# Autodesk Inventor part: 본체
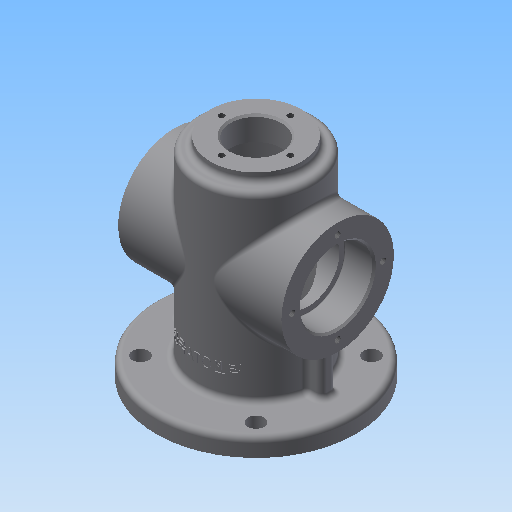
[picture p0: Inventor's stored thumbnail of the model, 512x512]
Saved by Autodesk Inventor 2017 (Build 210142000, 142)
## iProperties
Created: 2020-05
Part Number: 본체
Material: 알루미늄 6061
Document SubType Name: Modeling
Designer: mduedu
Density: 2.71 g/cm^3
Appearance: 기본값
Mass: 777.255 g
Surface Area: 687.925 cm^2
Volume: 286.81 cm^3
Author: mduedu
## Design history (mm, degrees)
sketch "스케치1"
  geometry: C1 r 32 at (0, 0); 1 further point
  constraints: 1 centre point, 1 coincident
  dimensions: "d0" = 64 diameter of C1
extrude "돌출1" new body sketch "스케치1" distance "d1" = 110; taper "d2" = 0 deg
feature "쉘1" dims "d3" = 8
fillet "모깎기1" dims "d4" = 3
fillet "모깎기2" dims "d5" = 3
sketch "스케치2"
  geometry: C1 r 25 at (0, 0); 1 further point
  constraints: 1 centre point, 1 coincident
  dimensions: "d6" = 50 diameter of C1
extrude "돌출2" join sketch "스케치2" distance "d7" = 5; taper "d8" = 0 deg
sketch "스케치3"
  geometry: C1 r 14 at (0, 0); 1 further point
  constraints: 1 centre point, 1 coincident
  dimensions: "d9" = 28 diameter of C1
extrude "돌출3" cut sketch "스케치3" stored distance "d10" = 5; taper "d11" = 0 deg
fillet "모깎기3" dims "d12" = 3
sketch "스케치4"
  geometry: C1 r 32 at (0, 0) reference; C2 r 55 at (0, 0); 1 further point
  constraints: 1 centre point, 1 coincident
  dimensions: "d13" = 110 diameter of C2
extrude "돌출4" join sketch "스케치4" distance "d14" = 10; taper "d15" = 0 deg
sketch "스케치5"
  geometry: L1 (0, 0)-(-31.82, 31.82); L2 (0, 0)-(-45, 0); A1 r 45 centre (0, 0) between (-31.82, 31.82) and (-45, 0); 1 further point
  constraints: 4 end point, 2 point on circle, 1 centre point, 1 coincident, 1 horizontal
  dimensions: "d16" = 90 diameter of A1; "d71" = 45 deg angle of L1 L2
hole "구멍1" sketch "스케치5" at (-31.82, 31.82) diameter "d17" = 9; stored, may be unused: countersink angle "d21" = 90 deg, drill point angle "d23" = 118 deg; dims "d18" = 6, "d19" = 4, "d20" = 2, "d22" = 8
fillet "모깎기4" dims "d27" = 3
node "작업 평면1"
sketch "스케치6"
  geometry: L1 (0, 55)-(0, -55) reference; C1 r 31 at (-65, 0); 2 further points
  constraints: 1 centre point, 1 horizontal alignment, 1 midpoint
  dimensions: "d31" = 62 diameter of C1; "d32" = 65 distance from line of C1.centre L1
extrude "돌출5" join sketch "스케치6" stored distance "d33" = 10; taper "d34" = 0 deg
fillet "모깎기5" dims "d35" = 3
sketch "스케치7"
  geometry: C1 r 31 at (0, 0) reference; C2 r 20 at (0, 0); 1 further point
  constraints: 1 centre point, 1 coincident
  dimensions: "d36" = 40 diameter of C2
extrude "돌출6" cut sketch "스케치7" distance "d37" = 16; taper "d38" = 0 deg
sketch "스케치8"
  geometry: C1 r 20 at (0, 0) reference; C2 r 17 at (0, 0); 1 further point
  constraints: 1 centre point, 1 coincident
  dimensions: "d39" = 34 diameter of C2
extrude "돌출7" cut sketch "스케치8" stored distance "d40" = 15; taper "d41" = 0 deg
fillet "모깎기6" dims "d42" = 0.3
chamfer "모따기1" distance "d43" = 1; stored, may be unused: second distance "d44" = 2, angle "d45" = 45 deg
chamfer "모따기2" distance "d46" = 1; stored, may be unused: second distance "d47" = 2, angle "d48" = 45 deg
sketch "스케치9" dims "d49" = 50
  geometry: C1 r 31 at (0, 0) reference; 3 further points
  constraints: 2 vertical alignment, 1 coincident, 2 other
hole "구멍2" sketch "스케치9" at (0, 25) diameter "d50" = 3.242; stored, may be unused: countersink angle "d54" = 90 deg, drill point angle "d56" = 118 deg; dims "d51" = 7, "d52" = 4, "d53" = 2, "d55" = 9
sketch "스케치10" dims "d60" = 38
  geometry: 3 further points
  constraints: 2 vertical alignment, 1 coincident, 2 other
hole "구멍3" sketch "스케치10" at (0, 19) diameter "d61" = 3.242; stored, may be unused: countersink angle "d65" = 90 deg, drill point angle "d67" = 118 deg; dims "d62" = 8, "d63" = 4, "d64" = 2, "d66" = 10
sketch "스케치11"
  geometry: L1 (32, 31)-(32, 13) reference; L2 (35, 10)-(52, 10) reference; L3 (55, 7)-(55, 0) reference; L4 (55, 0)-(24, 0) reference; L5 (24, 0)-(24, 48) reference; L6 (24, 48)-(29, 48) reference; L7 (29, 48)-(29, 45.3) reference; L8 (29.3, 45)-(44, 45) reference; L9 (44, 45)-(45, 44) reference; L10 (45, 44)-(45, 41.621) reference; L11 (45, 41.621)-(36, 41.621) reference; L12 (36, 41.621)-(35.026, 40) reference; L13 (35.026, 40)-(36, 38.379) reference; L14 (36, 38.379)-(45, 38.379) reference; L15 (45, 38.379)-(45, 34) reference; L16 (45, 34)-(35, 34) reference; L17 (-32, 13)-(-32, 31) reference; L18 (-35, 34)-(-45, 34) reference; L19 (-45, 34)-(-45, 38.379) reference; L20 (-45, 38.379)-(-36, 38.379) reference; L21 (-36, 38.379)-(-35.026, 40) reference; L22 (-35.026, 40)-(-36, 41.621) reference; L23 (-36, 41.621)-(-45, 41.621) reference; L24 (-45, 41.621)-(-45, 44) reference; L25 (-45, 44)-(-44, 45) reference; L26 (-44, 45)-(-29.3, 45) reference; L27 (-29, 45.3)-(-29, 48) reference; L28 (-29, 48)-(-24, 48) reference; L29 (-24, 48)-(-24, 0) reference; L30 (-24, 0)-(-55, 0) reference; L31 (-55, 0)-(-55, 7) reference; L32 (-52, 10)-(-35, 10) reference; L33 (-25, 113)-(-25, 115) reference; L34 (-25, 115)-(-20.621, 115) reference; L35 (-20.621, 115)-(-20.621, 105) reference; L36 (-20.621, 105)-(-19, 104.026) reference; L37 (-19, 104.026)-(-17.379, 105) reference; L38 (-17.379, 105)-(-17.379, 115) reference; L39 (-17.379, 115)-(-15, 115) reference; L40 (-15, 115)-(-14, 114) reference; L41 (-14, 114)-(-14, 102) reference; L42 (-14, 102)-(-21, 102) reference; L43 (-24, 99)-(-24, 82) reference; L44 (-24, 82)-(-29, 82) reference; L45 (-29, 82)-(-29, 84.7) reference; L46 (-29.3, 85)-(-44, 85) reference; L47 (-44, 85)-(-45, 86) reference; L48 (-45, 86)-(-45, 88.379) reference; L49 (-45, 88.379)-(-36, 88.379) reference; L50 (-36, 88.379)-(-35.026, 90) reference; L51 (-35.026, 90)-(-36, 91.621) reference; L52 (-36, 91.621)-(-45, 91.621) reference; L53 (-45, 91.621)-(-45, 96) reference; L54 (-45, 96)-(-35, 96) reference; L55 (-32, 99)-(-32, 107) reference; L56 (-29, 110)-(-28, 110) reference; L57 (28, 110)-(29, 110) reference; L58 (32, 107)-(32, 99) reference; L59 (35, 96)-(45, 96) reference; L60 (45, 96)-(45, 91.621) reference; L61 (45, 91.621)-(36, 91.621) reference; L62 (36, 91.621)-(35.026, 90) reference; L63 (35.026, 90)-(36, 88.379) reference; L64 (36, 88.379)-(45, 88.379) reference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; A1 r 3 centre (35, 13) between (32, 13) and (35, 10) reference; A2 r 3 centre (52, 7) between (55, 7) and (52, 10) reference; A3 r 0.3 centre (29.3, 45.3) between (29, 45.3) and (29.3, 45) reference; A4 r 0.3 centre (-29.3, 45.3) between (-29.3, 45) and (-29, 45.3) reference; A5 r 3 centre (-52, 7) between (-52, 10) and (-55, 7) reference; A6 r 3 centre (-35, 13) between (-35, 10) and (-32, 13) reference; A7 r 3 centre (-28, 113) between (-28, 110) and (-25, 113) reference; A8 r 3 centre (-21, 99) between (-21, 102) and (-24, 99) reference; A9 r 0.3 centre (-29.3, 84.7) between (-29, 84.7) and (-29.3, 85) reference; A10 r 3 centre (-29, 107) between (-29, 110) and (-32, 107) reference; A11 r 3 centre (28, 113) between (25, 113) and (28, 110) reference; A12 r 3 centre (29, 107) between (32, 107) and (29, 110) reference; A13 r 0.3 centre (29.3, 84.7) between (29.3, 85) and (29, 84.7) reference; A14 r 3 centre (21, 99) between (24, 99) and (21, 102) reference; 1 further point
  constraints: 2 end point, 1 midpoint, 1 perpendicular, 1 point on line, 4 other
  dimensions: "d73" = 5 distance between parallel lines of L81 L19
feature "리브1" sketch "스케치11" dims "d74" = 1, "d75" = 8, "d76" = 0, "d77" = 0, "d78" = 1, "d79" = 1
fillet "모깎기7" dims "d80" = 3
fillet "모깎기8" dims "d81" = 3
node "작업 평면2"
sketch "스케치12"
  geometry: 2 further points
  constraints: 1 vertical alignment, 1 other
  dimensions: "d83" = 25 distance of point (0, 25) point (0, 0)
feature "엠보싱1" sketch "스케치12" dims "d0" = 64, "d84" = 0.5, "d85" = 0
node "솔리드1"
pattern_circular "원형 패턴1" dims angle "d25" = 360 deg
mirror "대칭1"
mirror "대칭2"
pattern_circular "원형 패턴2" dims angle "d58" = 360 deg
mirror "대칭3"
pattern_circular "원형 패턴3" dims angle "d69" = 360 deg
mirror "대칭4"
node "투영된 루프1"
node "투영된 루프2"
node "절단 모서리 투영1"
other parameters: "d30" = -45
